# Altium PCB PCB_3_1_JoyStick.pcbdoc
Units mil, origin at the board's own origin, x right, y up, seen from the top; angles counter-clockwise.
Board outline 1287.4 x 1447.4 mil, 2 copper layers (Top Layer, Bottom Layer), stack 62.206 mil thick; 2 components, 5 nets, 21 pads, 6 vias.
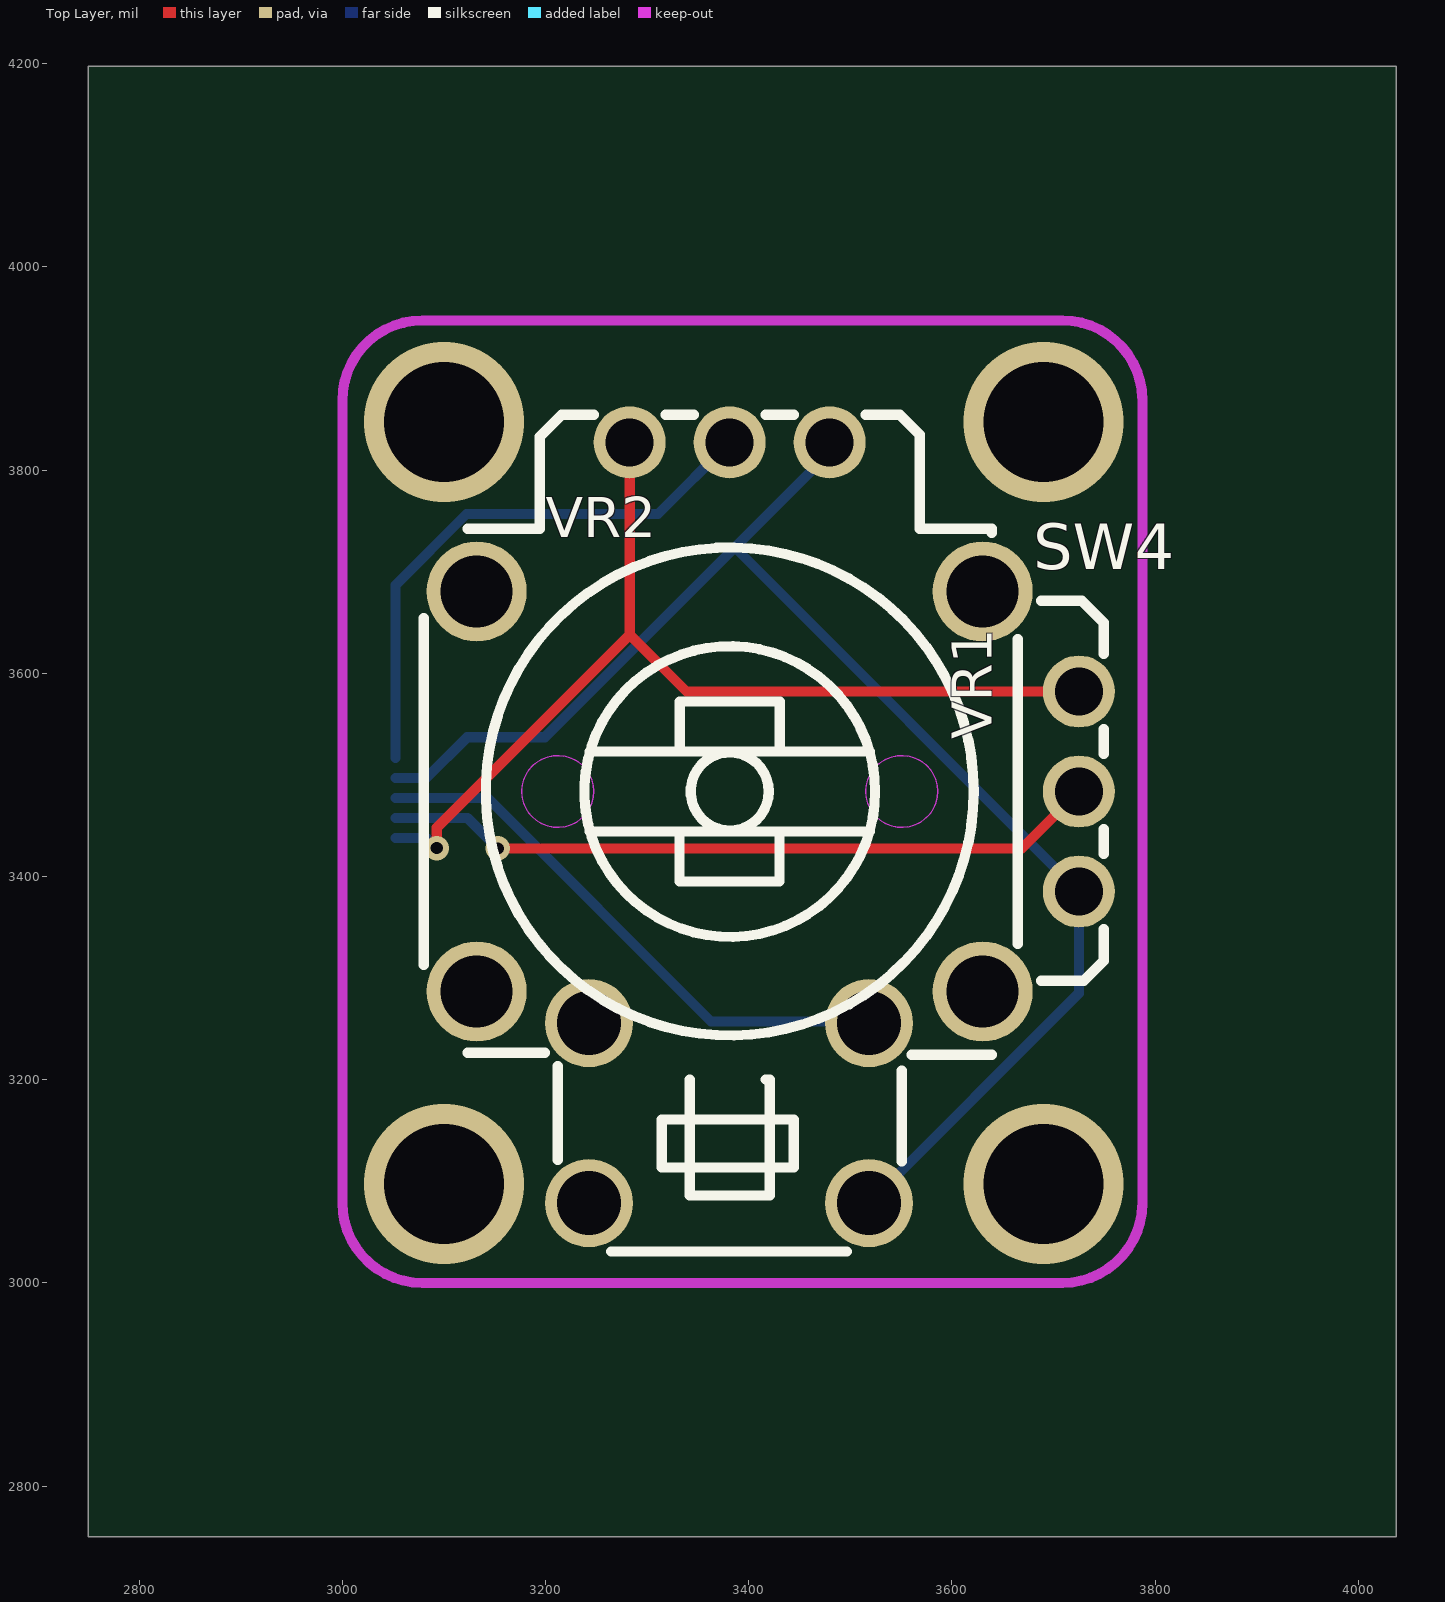
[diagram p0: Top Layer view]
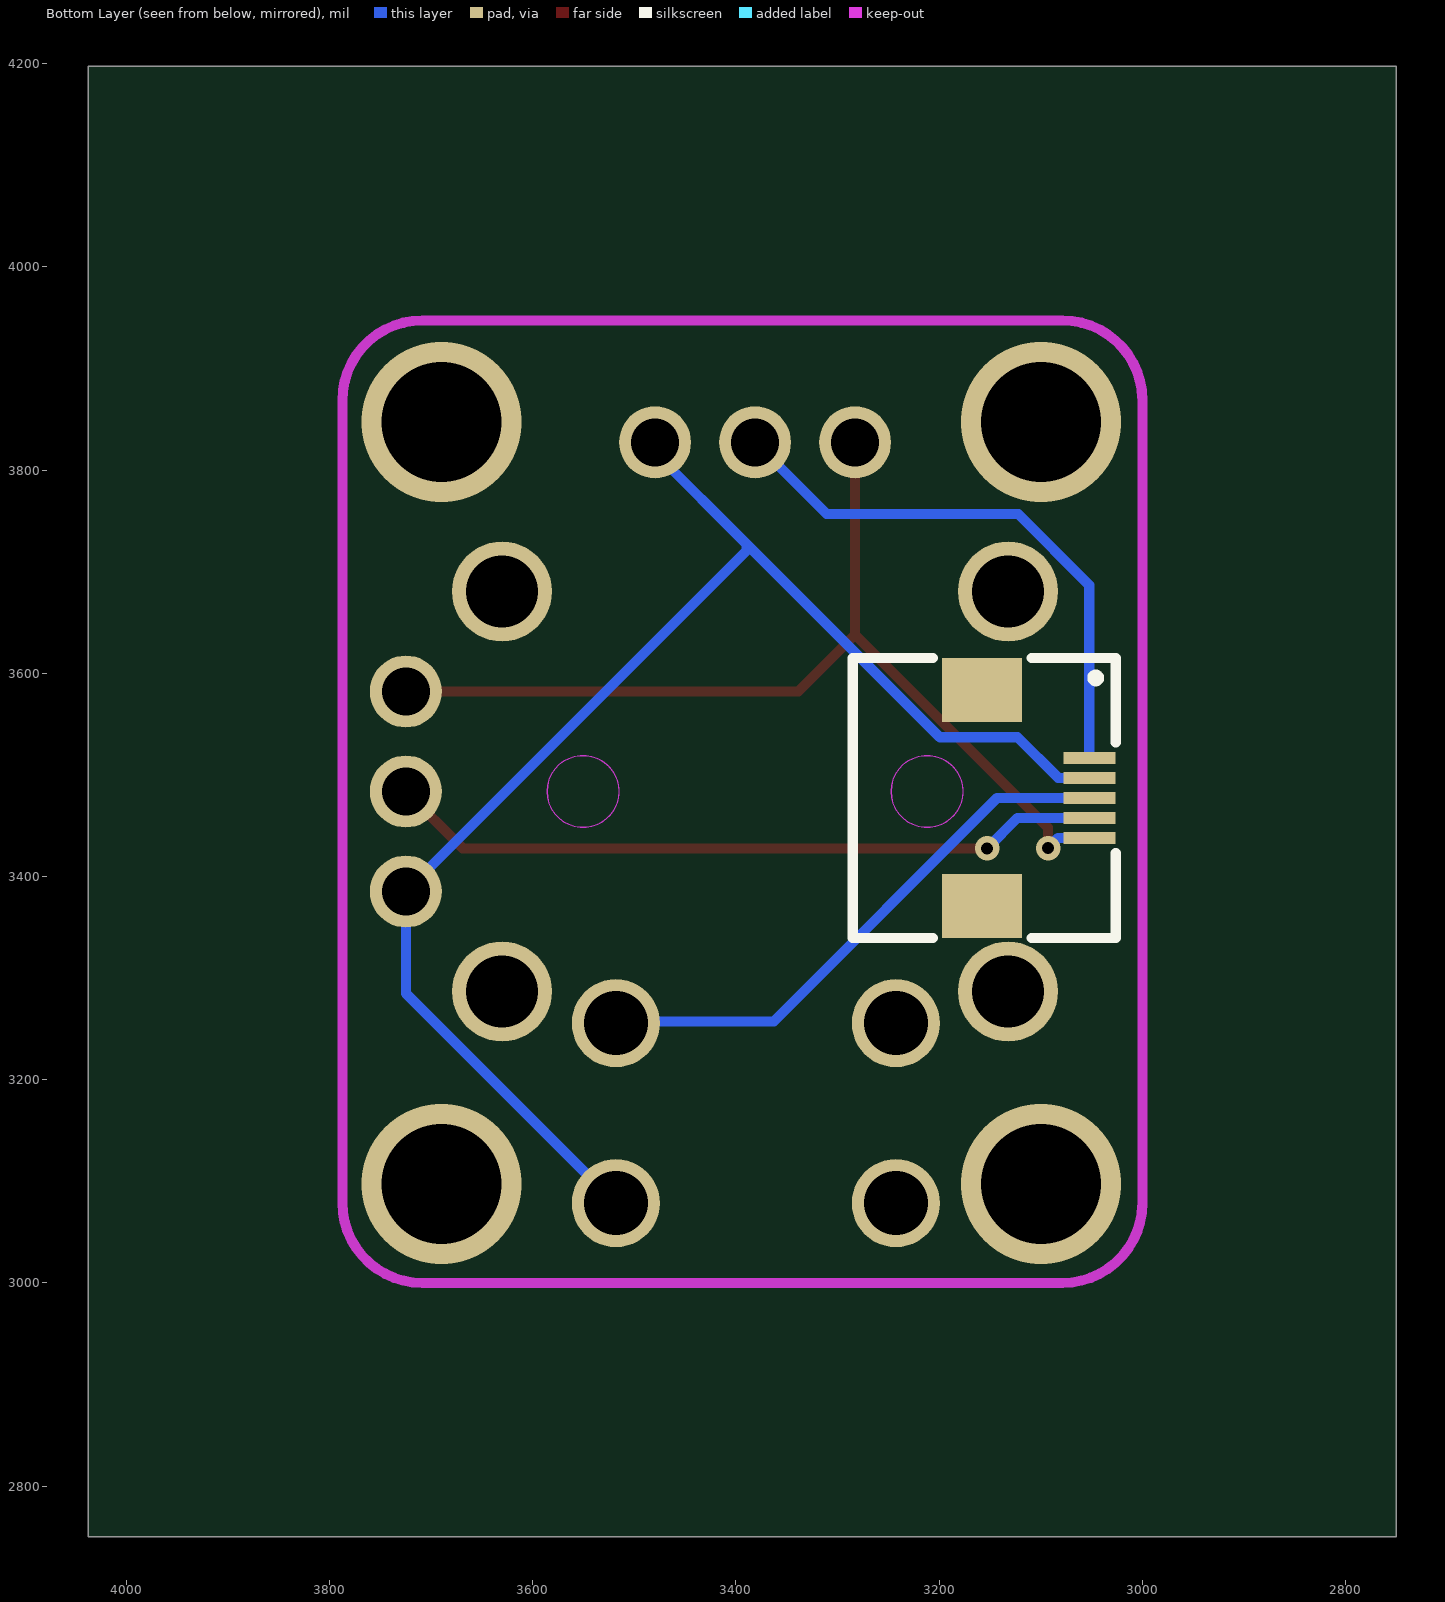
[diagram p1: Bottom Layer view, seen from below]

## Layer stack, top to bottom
Top Solder Mask Layer: solder mask 0.394, Dk 3.3
Top Layer: signal copper 1.379
Dielectric1: surface 59.449, FR4, Dk 4.5
Bottom Layer: signal copper 1.378
Bottom Solder Mask Layer: solder mask 0.394, Dk 3.3

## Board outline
4037.4,2750 2750,2750 2750,4197.4 4037.4,4197.4

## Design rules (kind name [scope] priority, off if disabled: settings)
BoardOutlineClearance copperThickness1oz [All] p0: genericclearance=10 ignorepadtopadclearanceinfootprint=FALSE except(0: Arc-SplitContinuation Track-SplitContinuation SMDPad-SplitContinuation THPad-SplitContinuation Via-SplitContinuation Fill-SplitContinuation Poly-SplitContinuation Region-SplitContinuation Text-SplitContinuation)
BoardOutlineClearance copperThickness2oz [All] p0: genericclearance=10 ignorepadtopadclearanceinfootprint=FALSE except(0: Arc-SplitContinuation Track-SplitContinuation SMDPad-SplitContinuation THPad-SplitContinuation Via-SplitContinuation Fill-SplitContinuation Poly-SplitContinuation Region-SplitContinuation Text-SplitContinuation)
BoardOutlineClearance otherClearance [All] p0: genericclearance=10 ignorepadtopadclearanceinfootprint=FALSE except(0: Arc-SplitContinuation Track-SplitContinuation SMDPad-SplitContinuation THPad-SplitContinuation Via-SplitContinuation Fill-SplitContinuation Poly-SplitContinuation Region-SplitContinuation Text-SplitContinuation)
Clearance copperThickness1oz [All] p1: gap=7 ignorepadtopadclearanceinfootprint=FALSE
Clearance copperThickness2oz [All] p1: gap=7 ignorepadtopadclearanceinfootprint=FALSE
Clearance otherClearance [All] p1: gap=7 ignorepadtopadclearanceinfootprint=FALSE
DiffPairsRouting differentialPair [All] p1: maxuncoupledlength=10 minlimit=6 maxlimit=Infinity mostfreqgap=6 toplayer_minwidth=5 toplayer_prefwidth=10 toplayer_maxwidth=100 bottomlayer_minwidth=5 bottomlayer_prefwidth=10 bottomlayer_maxwidth=100
PasteMaskExpansion pasteMaskExpansion [All] p1: expansion=0
PlaneConnect innerPlane [All] p1: planeconnectstyle=Relief reliefexpansion=20 reliefentries=4 reliefconductorwidth=10 reliefairgap=10
PolygonConnect copperRegion [All] p1: connectstyle=Relief reliefentries=4 reliefconductorwidth=10 polygonreliefangle="90 Angle" airgapwidth=10
RoutingVias viaSize [All] p1: viastyle="Through Hole" holewidth=12.0078 minholewidth=11.811 maxholewidth=248.0314 width=12.0078 minwidth=11.811 maxwidth=248.0314
SolderMaskExpansion solderMaskExpansion [IsVia] p1: useseparateexpansions=TRUE expansion=-1000 expansionbottom=-1000
SolderMaskExpansion solderMaskExpansion [All] p2: useseparateexpansions=TRUE expansion=2 expansionbottom=2
Width copperThickness1oz [All] p1: maxlimit=100 minlimit=5 preferedwidth=10
Width copperThickness2oz [All] p1: maxlimit=100 minlimit=8 preferedwidth=10

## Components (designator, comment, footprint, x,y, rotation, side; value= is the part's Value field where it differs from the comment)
SW4 "RKJXV1224005" SW-TH_RKJXV1224005 3428.59,3452.98 r0 top
? "AFC01-S05FCA-00" FPC-SMD_AFC01-S05FCA-00 3105,3477.4 r270 bottom

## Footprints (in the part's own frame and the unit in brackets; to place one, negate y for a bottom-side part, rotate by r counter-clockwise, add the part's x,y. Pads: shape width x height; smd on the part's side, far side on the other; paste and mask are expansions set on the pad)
FPC-SMD_AFC01-S05FCA-00 [mm]
  rect 0.3x1.3 smd paste+0 mask+0.051: 1(-1,1.34) 2(-0.5,1.34) 3(0,1.34) 4(0.5,1.34) 5(1,1.34)
  rect 1.6x2 smd paste+0 mask+0.051: 6(2.7,-1.34) 7(-2.7,-1.34)
  silkscreen extent -3.5,-4.57 3.5,2
SW-TH_RKJXV1224005 [mm]
  round 1.8 hole 1.2: 1(7.527,-1.719) 2(7.527,0.781) 3(7.527,3.281) 4(1.297,9.511) 5(-1.202,9.511) 6(-3.703,9.511)
  round 2.5 hole 1.8: 7(-7.527,5.781) 8(-7.527,-4.219) 9(5.123,-4.219) 10(5.123,5.781)
  round 2.2 hole 1.6: a(-4.722,-5.011) b(-4.722,-9.511) c(2.278,-5.011) d(2.278,-9.511)
  Board Outline Layer circle w0.003: c-5.503,0.781 r0.9
  Board Outline Layer circle w0.003: c3.097,0.781 r0.9
  Board Outline Layer region: -4.603,0.781 -4.692,0.39 -4.942,0.077 -5.302,-0.097 -5.703,-0.097 -6.064,0.077 -6.314,0.39 -6.403,0.781 -6.403,0.781 -6.314,1.171 -6.064,1.485 -5.703,1.658 -5.302,1.658 -4.942,1.485 -4.692,1.171 -4.603,0.781
  Board Outline Layer region: -4.603,0.781 -4.692,0.39 -4.942,0.077 -5.302,-0.097 -5.703,-0.097 -6.064,0.077 -6.314,0.39 -6.403,0.781 -6.403,0.781 -6.314,1.171 -6.064,1.485 -5.703,1.658 -5.302,1.658 -4.942,1.485 -4.692,1.171 -4.603,0.781
  Board Outline Layer region: 3.997,0.781 3.908,0.39 3.658,0.077 3.298,-0.097 2.897,-0.097 2.536,0.077 2.286,0.39 2.197,0.781 2.197,0.781 2.286,1.171 2.536,1.485 2.897,1.658 3.298,1.658 3.658,1.485 3.908,1.171 3.997,0.781
  Board Outline Layer region: 3.997,0.781 3.908,0.39 3.658,0.077 3.298,-0.097 2.897,-0.097 2.536,0.077 2.286,0.39 2.197,0.781 2.197,0.781 2.286,1.171 2.536,1.485 2.897,1.658 3.298,1.658 3.658,1.485 3.908,1.171 3.997,0.781
  silkscreen extent -8.85,-10.72 8.15,10.2

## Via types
v1: diameter 157.48, hole 118.11, Top Layer to Bottom Layer, 4 vias
v2: diameter 24.02, hole 12.01, Top Layer to Bottom Layer, 2 vias

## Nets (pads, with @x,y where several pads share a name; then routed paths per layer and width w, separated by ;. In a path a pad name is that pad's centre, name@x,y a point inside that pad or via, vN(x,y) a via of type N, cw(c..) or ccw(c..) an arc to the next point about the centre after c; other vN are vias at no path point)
$1N1: ?.4 SW4.2 | length 708.3
  Top Layer w10: v2(3152.83,3427.71) 3668.93,3427.71 SW4.2
  Bottom Layer w10: ?.4 3122.83,3457.71 v2(3152.83,3427.71)
$1N2: ?.3 SW4.c | length 557.9
  Bottom Layer w10: ?.3 3142.83,3477.4 3362.83,3257.4 3516.58,3257.4 SW4.c
$1N3: ?.1 SW4.5 | length 557.3
  Bottom Layer w10: ?.1 3052.24,3686.77 3122.24,3756.77 3310.6,3756.77 SW4.5
$1N4: ?.2 SW4.1 SW4.4 SW4.d | length 1443.3
  Bottom Layer w10: ?.2 3082.83,3497.08 3122.83,3537.08 3199.33,3537.08 3389.33,3727.08 ; SW4.4 3479.66,3817.42 3389.33,3727.08 ; SW4.d 3724.94,3285.18 SW4.1 3389.33,3720.9 3389.33,3727.08
$1N5: ?.5 SW4.3 SW4.6 | length 988.1
  Top Layer w10: v2(3092.83,3428.03) 3092.83,3448.03 3282.83,3638.03 ; SW4.6 3282.83,3638.03 ; SW4.3 3338.72,3582.14 3282.83,3638.03
  Bottom Layer w10: ?.5 3082.83,3438.03 v2(3092.83,3428.03)
pads on no net: ?.6 ?.7 SW4.7 SW4.8 SW4.9 SW4.10 SW4.a SW4.b
copper on no net:
  other v1: 3100,3097.4 3690,3097.4 3100,3847.4 3690,3847.4

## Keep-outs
Board Outline Layer:
  lines w10: 3000,3078.74 ccw(c3078.74,3078.74) 3078.74,3000 3708.66,3000 ccw(c3708.66,3078.74) 3787.4,3078.74 3787.4,3868.66 ccw(c3708.66,3868.66) 3708.66,3947.4 3078.74,3947.4 ccw(c3078.74,3868.66) 3000,3868.66 3000,3078.74

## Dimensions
3100,4102.05 to 3690,4102.05 on Document Layer
3960,3847.4 to 3960,3097.4 on Document Layer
